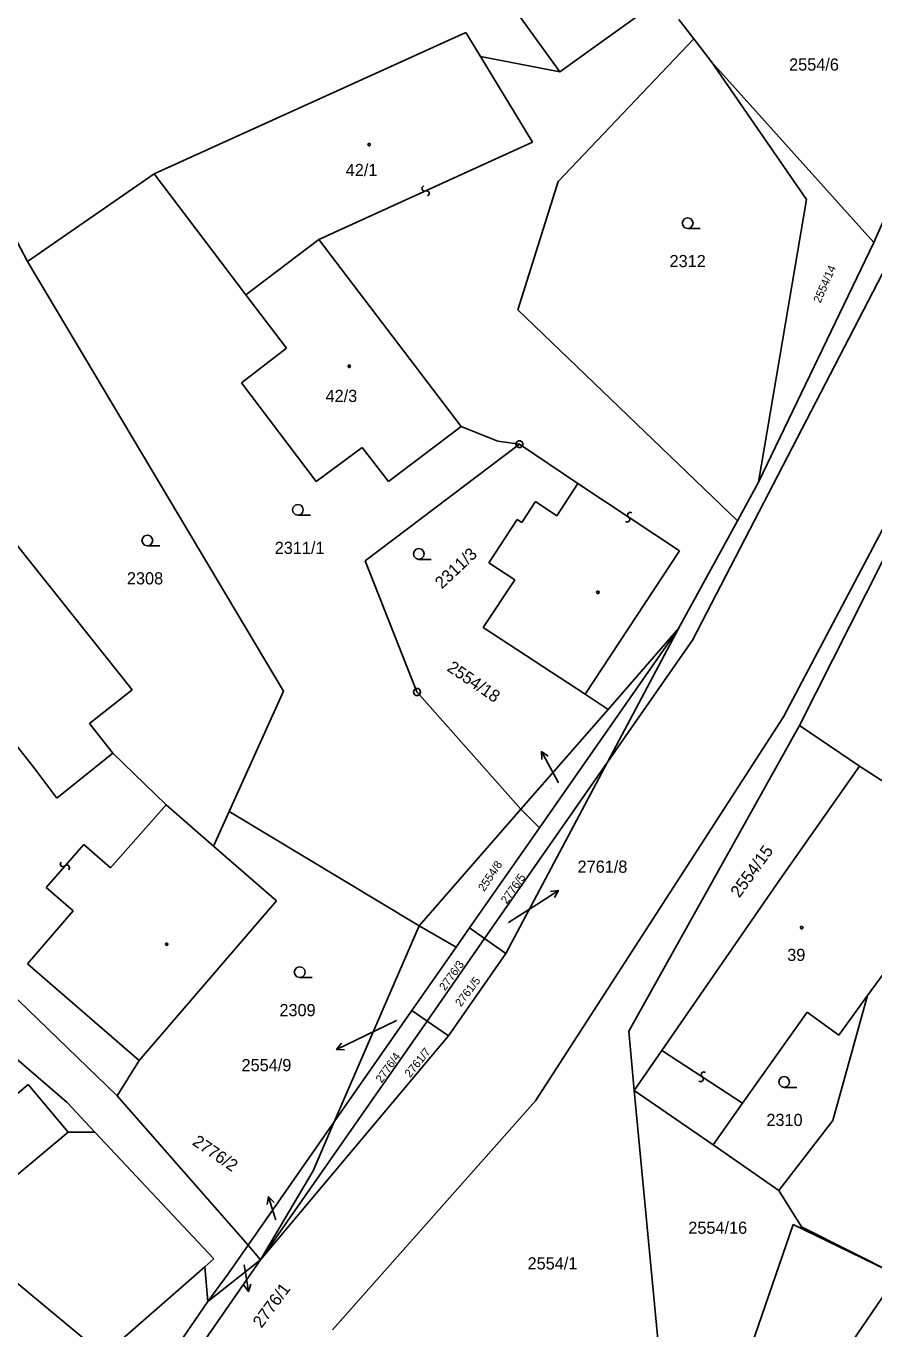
# Model space of a CAD drawing. Extents: x -747792 to -745414, y -1093712 to -1091463.
# Drawn here: x -746688.5 to -746629.3, y -1093057.2 to -1092966.2 of the extents above; entities that cross this region are included whole.
import ezdxf

# ---------------------------------------------------------------- set-up
doc = ezdxf.new("R2010")
doc.units = 0
for name, color, linetype in [('Pracovní_bod JDTM STC_VC', 7, 'Continuous'), ('Pracovní_bod JDTM STC_VC - výška', 7, 'Continuous'), ('Pracovní_bod JDTM STC_VC - číslo', 7, 'Continuous'), ('Pracovní_bod NN - výška', 7, 'Continuous'), ('Pracovní_bod polohopisu', 7, 'Continuous'), ('Pracovní_bod polohopisu - výška', 7, 'Continuous'), ('Pracovní_bod VN - výška', 7, 'Continuous')]:
    doc.layers.add(name, color=color, linetype=linetype)

msp = doc.modelspace()

# ---------------------------------------------------------------- linework, layer by layer
at = {"layer": 'Pracovní_bod JDTM STC_VC - výška'}
for points in [[(-746664.52, -1092974.425), (-746664.47, -1092974.435), (-746664.445, -1092974.48), (-746664.435, -1092974.51), (-746664.445, -1092974.555), (-746664.485, -1092974.59), (-746664.52, -1092974.595), (-746664.565, -1092974.58), (-746664.595, -1092974.55), (-746664.605, -1092974.51), (-746664.595, -1092974.465), (-746664.555, -1092974.43)], [(-746665.91, -1092989.905), (-746665.86, -1092989.915), (-746665.835, -1092989.96), (-746665.825, -1092989.99), (-746665.835, -1092990.035), (-746665.875, -1092990.07), (-746665.91, -1092990.075), (-746665.955, -1092990.06), (-746665.985, -1092990.03), (-746665.995, -1092989.99), (-746665.985, -1092989.945), (-746665.945, -1092989.91)], [(-746648.495, -1093005.705), (-746648.45, -1093005.78), (-746648.495, -1093005.855), (-746648.585, -1093005.855), (-746648.63, -1093005.78), (-746648.585, -1093005.705)], [(-746634.31, -1093029.115), (-746634.26, -1093029.125), (-746634.235, -1093029.17), (-746634.225, -1093029.2), (-746634.235, -1093029.245), (-746634.275, -1093029.28), (-746634.31, -1093029.285), (-746634.355, -1093029.27), (-746634.385, -1093029.24), (-746634.395, -1093029.2), (-746634.385, -1093029.155), (-746634.345, -1093029.12)], [(-746678.615, -1093030.285), (-746678.57, -1093030.36), (-746678.615, -1093030.435), (-746678.705, -1093030.435), (-746678.75, -1093030.36), (-746678.705, -1093030.285)]]:
    msp.add_lwpolyline(points, close=True, dxfattribs=at)
at = {"layer": 'Pracovní_bod JDTM STC_VC - číslo'}
for points in [[(-746642.27, -1092980.37), (-746642.46, -1092980.32), (-746642.595, -1092980.18), (-746642.645, -1092979.995), (-746642.595, -1092979.81), (-746642.46, -1092979.67), (-746642.27, -1092979.62), (-746642.08, -1092979.67), (-746641.945, -1092979.81), (-746641.895, -1092979.995), (-746641.945, -1092980.18), (-746642.08, -1092980.32), (-746642.27, -1092980.37), (-746641.395, -1092980.37)], [(-746669.49, -1093000.4), (-746669.68, -1093000.35), (-746669.815, -1093000.21), (-746669.865, -1093000.025), (-746669.815, -1092999.84), (-746669.68, -1092999.7), (-746669.49, -1092999.65), (-746669.3, -1092999.7), (-746669.165, -1092999.84), (-746669.115, -1093000.025), (-746669.165, -1093000.21), (-746669.3, -1093000.35), (-746669.49, -1093000.4), (-746668.615, -1093000.4)], [(-746680.01, -1093002.53), (-746680.2, -1093002.48), (-746680.335, -1093002.34), (-746680.385, -1093002.155), (-746680.335, -1093001.97), (-746680.2, -1093001.83), (-746680.01, -1093001.78), (-746679.82, -1093001.83), (-746679.685, -1093001.97), (-746679.635, -1093002.155), (-746679.685, -1093002.34), (-746679.82, -1093002.48), (-746680.01, -1093002.53), (-746679.135, -1093002.53)], [(-746661.05, -1093003.48), (-746661.24, -1093003.43), (-746661.375, -1093003.29), (-746661.425, -1093003.105), (-746661.375, -1093002.92), (-746661.24, -1093002.78), (-746661.05, -1093002.73), (-746660.86, -1093002.78), (-746660.725, -1093002.92), (-746660.675, -1093003.105), (-746660.725, -1093003.29), (-746660.86, -1093003.43), (-746661.05, -1093003.48), (-746660.175, -1093003.48)], [(-746669.37, -1093032.69), (-746669.56, -1093032.64), (-746669.695, -1093032.5), (-746669.745, -1093032.315), (-746669.695, -1093032.13), (-746669.56, -1093031.99), (-746669.37, -1093031.94), (-746669.18, -1093031.99), (-746669.045, -1093032.13), (-746668.995, -1093032.315), (-746669.045, -1093032.5), (-746669.18, -1093032.64), (-746669.37, -1093032.69), (-746668.495, -1093032.69)], [(-746635.53, -1093040.36), (-746635.72, -1093040.31), (-746635.855, -1093040.17), (-746635.905, -1093039.985), (-746635.855, -1093039.8), (-746635.72, -1093039.66), (-746635.53, -1093039.61), (-746635.34, -1093039.66), (-746635.205, -1093039.8), (-746635.155, -1093039.985), (-746635.205, -1093040.17), (-746635.34, -1093040.31), (-746635.53, -1093040.36), (-746634.655, -1093040.36)]]:
    msp.add_lwpolyline(points, dxfattribs=at)
at = {"layer": 'Pracovní_bod NN - výška'}
for points in [[(-746651.2, -1092969.42), (-746668.44, -1092945.56)], [(-746645.02, -1092965.01), (-746651.2, -1092969.42)], [(-746622.01, -1092964.92), (-746629.27, -1092981.35)], [(-746642.89, -1092965.77), (-746641.85, -1092967.12)], [(-746679.53, -1092976.56), (-746657.76, -1092966.69)], [(-746656.75, -1092968.35), (-746657.76, -1092966.69)], [(-746641.85, -1092967.12), (-746651.31, -1092977.08)], [(-746641.85, -1092967.12), (-746640.6, -1092968.74)], [(-746651.2, -1092969.42), (-746656.75, -1092968.35)], [(-746633.98, -1092978.34), (-746640.6, -1092968.74)], [(-746640.6, -1092968.74), (-746629.27, -1092981.35)], [(-746688.38, -1092982.68), (-746679.53, -1092976.56)], [(-746679.53, -1092976.56), (-746673.12, -1092985.01)], [(-746651.31, -1092977.08), (-746654.14, -1092986.05)], [(-746637.33, -1092998.1), (-746633.98, -1092978.34)], [(-746689.35, -1092980.81), (-746688.38, -1092982.68)], [(-746673.12, -1092985.01), (-746668.04, -1092981.15)], [(-746668.04, -1092981.15), (-746658.08, -1092994.19)], [(-746629.27, -1092981.35), (-746637.33, -1092998.1)], [(-746670.51, -1093012.69), (-746688.38, -1092982.68)], [(-746628.34, -1092982.88), (-746641.93, -1093009.12)], [(-746673.12, -1092985.01), (-746670.28, -1092988.74)], [(-746638.8, -1093000.8), (-746654.14, -1092986.05)], [(-746670.28, -1092988.74), (-746673.44, -1092991.14)], [(-746673.44, -1092991.14), (-746668.23, -1092998.04)], [(-746623.48, -1092991.57), (-746635.57, -1093014.47)], [(-746622.77, -1092991.94), (-746634.45, -1093015.09)], [(-746663.17, -1092998.05), (-746658.08, -1092994.19)], [(-746658.08, -1092994.19), (-746655.54, -1092995.23)], [(-746668.23, -1092998.04), (-746665, -1092995.67)], [(-746665, -1092995.67), (-746663.17, -1092998.05)], [(-746664.79, -1093003.58), (-746654.02, -1092995.43)], [(-746655.54, -1092995.23), (-746654.02, -1092995.43)], [(-746649.95, -1092998.19), (-746654.02, -1092995.43)], [(-746651.4, -1093000.44), (-746649.95, -1092998.19)], [(-746637.33, -1092998.1), (-746638.8, -1093000.8)], [(-746653.86, -1093000.91), (-746652.9, -1092999.45)], [(-746652.9, -1092999.45), (-746651.4, -1093000.44)], [(-746681.08, -1093012.59), (-746691.1, -1093000.02)], [(-746654.19, -1093000.69), (-746656.15, -1093003.72)], [(-746654.19, -1093000.69), (-746653.86, -1093000.91)], [(-746638.8, -1093000.8), (-746642.9, -1093008.31)], [(-746664.79, -1093003.58), (-746661.18, -1093012.74)], [(-746656.15, -1093003.72), (-746654.34, -1093004.91)], [(-746654.34, -1093004.91), (-746656.56, -1093008.25)], [(-746687.93, -1093018.03), (-746697.89, -1093005.45)], [(-746656.56, -1093008.25), (-746649.44, -1093012.9)], [(-746642.9, -1093008.31), (-746652.63, -1093022.24)], [(-746647.87, -1093017.65), (-746642.9, -1093008.31)], [(-746647.83, -1093013.96), (-746642.9, -1093008.31)], [(-746641.93, -1093009.12), (-746647.87, -1093017.65)], [(-746682.11, -1093040.96), (-746711.87, -1093012.22)], [(-746684.04, -1093014.94), (-746681.08, -1093012.59)], [(-746674.29, -1093021.09), (-746670.51, -1093012.69)], [(-746661.18, -1093012.74), (-746653.92, -1093020.93)], [(-746649.44, -1093012.9), (-746647.83, -1093013.96)], [(-746647.83, -1093013.96), (-746653.92, -1093020.93)], [(-746716.87, -1093014.48), (-746685.62, -1093041.42)], [(-746682.42, -1093017.02), (-746684.04, -1093014.94)], [(-746652.89, -1093041.3), (-746635.57, -1093014.47)], [(-746634.45, -1093015.09), (-746646.39, -1093036.43)], [(-746634.45, -1093015.09), (-746630.27, -1093017.93)], [(-746686.34, -1093020.15), (-746682.42, -1093017.02)], [(-746678.69, -1093020.62), (-746682.42, -1093017.02)], [(-746647.87, -1093017.65), (-746656.45, -1093029.96)], [(-746654.98, -1093031), (-746647.87, -1093017.65)], [(-746687.93, -1093018.03), (-746686.34, -1093020.15)], [(-746630.27, -1093017.93), (-746635.8, -1093025.83)], [(-746630.27, -1093017.93), (-746624.42, -1093021.7)], [(-746675.38, -1093023.52), (-746678.69, -1093020.62)], [(-746675.38, -1093023.52), (-746674.29, -1093021.09)], [(-746674.29, -1093021.09), (-746661.03, -1093029.07)], [(-746653.92, -1093020.93), (-746661.03, -1093029.07)], [(-746653.92, -1093020.93), (-746652.63, -1093022.24)], [(-746652.63, -1093022.24), (-746657.5, -1093029.22)], [(-746670.99, -1093027.34), (-746675.38, -1093023.52)], [(-746635.8, -1093025.83), (-746644.07, -1093037.78)], [(-746680.59, -1093038.48), (-746670.99, -1093027.34)], [(-746666.96, -1093042.78), (-746661.03, -1093029.07)], [(-746661.03, -1093029.07), (-746658.43, -1093030.56)], [(-746657.5, -1093029.22), (-746658.43, -1093030.56)], [(-746657.5, -1093029.22), (-746656.45, -1093029.96)], [(-746656.45, -1093029.96), (-746660.47, -1093035.73)], [(-746656.45, -1093029.96), (-746654.98, -1093031)], [(-746629.7, -1093033.95), (-746626.95, -1093030.17)], [(-746658.43, -1093030.56), (-746661.53, -1093035)], [(-746654.98, -1093031), (-746658.98, -1093036.77)], [(-746632.12, -1093042.68), (-746629.7, -1093033.95)], [(-746631.72, -1093036.71), (-746629.7, -1093033.95)], [(-746661.53, -1093035), (-746666.96, -1093042.78)], [(-746660.47, -1093035.73), (-746661.53, -1093035)], [(-746633.93, -1093035.1), (-746638.45, -1093041.47)], [(-746633.93, -1093035.1), (-746631.72, -1093036.71)], [(-746660.47, -1093035.73), (-746672.1, -1093052.41)], [(-746658.98, -1093036.77), (-746660.47, -1093035.73)], [(-746672.1, -1093052.41), (-746658.98, -1093036.77)], [(-746646.39, -1093036.43), (-746646, -1093040.57)], [(-746644.07, -1093037.78), (-746646, -1093040.57)], [(-746682.11, -1093040.96), (-746680.59, -1093038.48)], [(-746685.62, -1093041.42), (-746683.67, -1093043.49)], [(-746672.97, -1093051.39), (-746682.11, -1093040.96)], [(-746667.08, -1093057.29), (-746652.89, -1093041.3)], [(-746646, -1093040.57), (-746644.26, -1093058.92)], [(-746640.5, -1093044.37), (-746646, -1093040.57)], [(-746638.45, -1093041.47), (-746640.5, -1093044.37)], [(-746672.97, -1093051.39), (-746666.96, -1093042.78)], [(-746666.96, -1093042.78), (-746668.43, -1093046.18)], [(-746632.12, -1093042.68), (-746635.9, -1093047.56)], [(-746685.53, -1093043.5), (-746690.26, -1093047.45)], [(-746685.53, -1093043.5), (-746683.67, -1093043.49)], [(-746683.67, -1093043.49), (-746675.36, -1093052.34)], [(-746635.9, -1093047.56), (-746640.5, -1093044.37)], [(-746668.43, -1093046.18), (-746672.1, -1093052.41)], [(-746634.31, -1093050.11), (-746635.9, -1093047.56)], [(-746639.05, -1093061.97), (-746634.9, -1093049.93)], [(-746634.9, -1093049.93), (-746627.61, -1093053.49)], [(-746627.61, -1093053.49), (-746634.31, -1093050.11)], [(-746672.97, -1093051.39), (-746674.37, -1093053.39)], [(-746672.97, -1093051.39), (-746672.1, -1093052.41)], [(-746675.36, -1093052.34), (-746675.99, -1093052.89)], [(-746690.81, -1093052.63), (-746683.06, -1093059.07)], [(-746675.99, -1093052.89), (-746683.06, -1093059.07)], [(-746672.1, -1093052.41), (-746678.75, -1093061.97)], [(-746675.78, -1093055.31), (-746675.99, -1093052.89)], [(-746675.78, -1093055.31), (-746672.1, -1093052.41)], [(-746674.37, -1093053.39), (-746675.78, -1093055.31)], [(-746642.63, -1093075.5), (-746627.61, -1093053.49)], [(-746675.78, -1093055.31), (-746679.93, -1093061.36)]]:
    msp.add_lwpolyline(points, dxfattribs=at)
at = {"layer": 'Pracovní_bod polohopisu'}
for points in [[(-746656.75, -1092968.35), (-746653.1, -1092974.33)], [(-746668.04, -1092981.15), (-746653.1, -1092974.33)], [(-746660.703, -1092977.389), (-746660.819, -1092977.496), (-746660.809, -1092977.662), (-746660.689, -1092977.756), (-746660.436, -1092977.734), (-746660.323, -1092977.836), (-746660.326, -1092977.997), (-746660.437, -1092978.091)], [(-746649.95, -1092998.19), (-746642.83, -1093002.88)], [(-746646.163, -1093000.236), (-746646.316, -1093000.195), (-746646.451, -1093000.291), (-746646.467, -1093000.443), (-746646.313, -1093000.646), (-746646.34, -1093000.795), (-746646.478, -1093000.878), (-746646.617, -1093000.834)], [(-746649.44, -1093012.9), (-746642.83, -1093002.88)], [(-746678.69, -1093020.62), (-746682.58, -1093025.02)], [(-746684.45, -1093023.39), (-746687.08, -1093026.39)], [(-746682.58, -1093025.02), (-746684.45, -1093023.39)], [(-746685.5, -1093025.156), (-746685.438, -1093025.01), (-746685.515, -1093024.863), (-746685.663, -1093024.827), (-746685.885, -1093024.951), (-746686.03, -1093024.904), (-746686.093, -1093024.756), (-746686.03, -1093024.624)], [(-746687.08, -1093026.39), (-746685.2, -1093028.04)], [(-746685.2, -1093028.04), (-746688.39, -1093031.73)], [(-746688.39, -1093031.73), (-746680.59, -1093038.48)], [(-746638.45, -1093041.47), (-746644.07, -1093037.78)], [(-746641.487, -1093039.925), (-746641.334, -1093039.965), (-746641.199, -1093039.869), (-746641.183, -1093039.717), (-746641.337, -1093039.515), (-746641.31, -1093039.365), (-746641.172, -1093039.282), (-746641.033, -1093039.325)], [(-746692.29, -1093043.52), (-746688.34, -1093040.15)], [(-746688.34, -1093040.15), (-746685.53, -1093043.5)]]:
    msp.add_lwpolyline(points, dxfattribs=at)
at = {"layer": 'Pracovní_bod polohopisu - výška'}
for points in [[(-746652.479, -1093016.904), (-746651.76, -1093018.22)], [(-746652.459, -1093017.462), (-746652.479, -1093016.904), (-746652.02, -1093017.223)], [(-746651.29, -1093019.08), (-746651.76, -1093018.22)], [(-746651.298, -1093026.61), (-746652.56, -1093027.42)], [(-746651.854, -1093026.669), (-746651.298, -1093026.61), (-746651.583, -1093027.09)], [(-746654.79, -1093028.85), (-746652.56, -1093027.42)], [(-746662.61, -1093035.69), (-746665.44, -1093037.07)], [(-746666.789, -1093037.726), (-746665.44, -1093037.07)], [(-746666.23, -1093037.732), (-746666.789, -1093037.726), (-746666.449, -1093037.283)], [(-746671.639, -1093048.551), (-746671.55, -1093047.999), (-746671.162, -1093048.401)], [(-746671.55, -1093047.999), (-746671.1, -1093049.43)], [(-746671.04, -1093049.62), (-746671.1, -1093049.43)], [(-746673.24, -1093052.78), (-746673.18, -1093053.15)], [(-746672.944, -1093054.631), (-746673.18, -1093053.15)], [(-746672.776, -1093054.098), (-746672.944, -1093054.631), (-746673.27, -1093054.177)]]:
    msp.add_lwpolyline(points, dxfattribs=at)
at = {"layer": 'Pracovní_bod VN - výška'}
for points in [[(-746653.945, -1092995.19), (-746653.82, -1092995.285), (-746653.77, -1092995.43), (-746653.82, -1092995.575), (-746653.945, -1092995.67), (-746654.095, -1092995.67), (-746654.22, -1092995.575), (-746654.27, -1092995.43), (-746654.22, -1092995.285), (-746654.095, -1092995.19)], [(-746661.105, -1093012.5), (-746660.98, -1093012.595), (-746660.93, -1093012.74), (-746660.98, -1093012.885), (-746661.105, -1093012.98), (-746661.255, -1093012.98), (-746661.38, -1093012.885), (-746661.43, -1093012.74), (-746661.38, -1093012.595), (-746661.255, -1093012.5)]]:
    msp.add_lwpolyline(points, close=True, dxfattribs=at)
for points in [[(-746654.045, -1092995.43), (-746653.995, -1092995.43)], [(-746661.205, -1093012.74), (-746661.155, -1093012.74)]]:
    msp.add_lwpolyline(points, dxfattribs=at)

# ---------------------------------------------------------------- texts
at = {"layer": 'Pracovní_bod JDTM STC_VC'}
for s, height, p in [('2554/6', 0.85, (-746635.185, -1092969.34)), ('42/1', 0.85, (-746666.155, -1092976.71)), ('2312', 0.85, (-746643.535, -1092983.07)), ('42/3', 0.85, (-746667.562, -1092992.49)), ('2311/1', 0.85, (-746671.11, -1093003.1)), ('2308', 0.85, (-746681.436, -1093005.23)), ('2554/18', 0.05, (-746651.94, -1093019.5)), ('39', 0.85, (-746635.316, -1093031.53)), ('2309', 0.85, (-746670.785, -1093035.39)), ('2554/9', 0.05, (-746662.736, -1093035.69)), ('2310', 0.85, (-746636.771, -1093043.06)), ('2776/2', 0.05, (-746671.163, -1093049.62)), ('2554/16', 0.85, (-746642.226, -1093050.59)), ('2554/1', 0.85, (-746653.451, -1093053.08)), ('2776/1', 0.05, (-746673.351, -1093052.78))]:
    msp.add_text(s, height=height, dxfattribs=at).set_placement(p)
for s, height, rotation, p in [('2554/14', 0.57, 66.4631, (-746633, -1092985.624)), ('2311/3', 0.85, 43.31561, (-746659.437, -1093005.59)), ('2554/15', 0.85, 53.97262, (-746638.666, -1093027.172)), ('2554/8', 0.57, 56.32175, (-746656.481, -1093026.723)), ('2776/5', 0.57, 54.77477, (-746654.905, -1093027.59)), ('2761/8', 0.05, 52.76941, (-746654.858, -1093028.94)), ('2776/3', 0.57, 54.14451, (-746659.215, -1093033.652)), ('2761/5', 0.57, 52.82671, (-746658.111, -1093034.77)), ('2761/7', 0.57, 51.16513, (-746661.652, -1093039.714)), ('2776/4', 0.57, 54.71747, (-746663.647, -1093040.096))]:
    msp.add_text(s, height=height, rotation=rotation, dxfattribs=at).set_placement(p)
at = {"layer": 'Pracovní_bod polohopisu - výška'}
for s, rotation, p in [('2554/18', 325.72651, (-746659.142, -1093011.21)), ('2776/2', 325.44003, (-746676.93, -1093044.323)), ('2776/1', 53.51426, (-746672.037, -1093057.225))]:
    msp.add_text(s, height=0.85, rotation=rotation, dxfattribs=at).set_placement(p)
for s, p in [('2761/8', (-746649.96, -1093025.37)), ('2554/9', (-746673.43, -1093039.23))]:
    msp.add_text(s, height=0.85, dxfattribs=at).set_placement(p)

doc.saveas('drawing.dxf')
